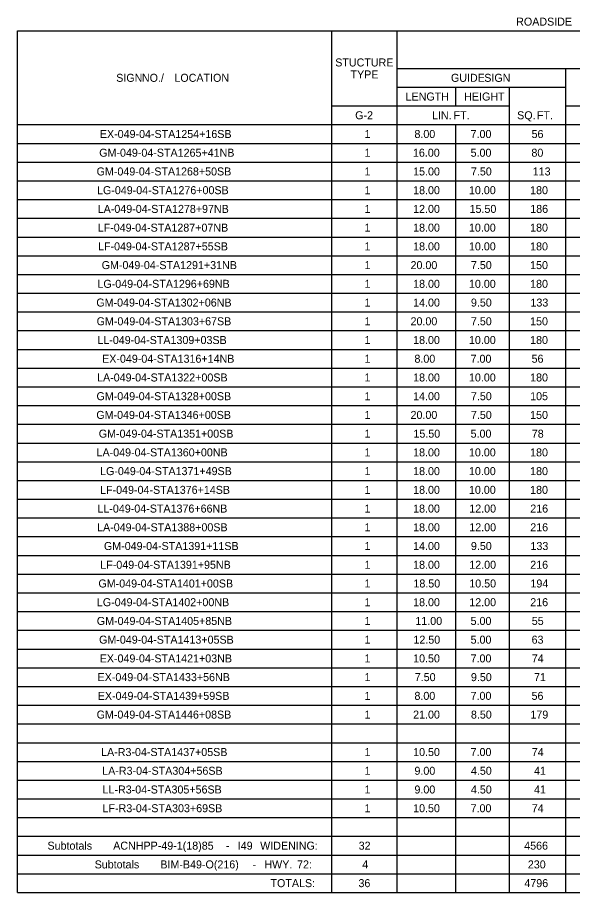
# Model space of a CAD drawing. Extents: x 1226631 to 1228126, y 151309 to 152305.
# Drawn here: x 1227303 to 1227650, y 151706 to 152253 of the extents above; entities that cross this region are included whole.
import ezdxf

# ---------------------------------------------------------------- set-up
doc = ezdxf.new("R2010")
doc.units = 0
doc.layers.add('R_Dimension', color=7, linetype='Continuous')

msp = doc.modelspace()

# ---------------------------------------------------------------- linework, layer by layer
at = {"layer": 'R_Dimension'}
for p, q in [((1227303.08, 152244.32), (1228086.49, 152244.32)), ((1227303.08, 151706.12), (1227303.08, 152244.32)), ((1227499.54, 151706.12), (1227499.54, 152244.32)), ((1227540.49, 151706.12), (1227540.49, 152244.32)), ((1227540.49, 152220.92), (1228086.49, 152220.92)), ((1227645.79, 151706.12), (1227645.79, 152220.92)), ((1227540.49, 152209.22), (1227645.79, 152209.22)), ((1227577.05, 152197.52), (1227577.05, 152209.22)), ((1227610.69, 151706.12), (1227610.69, 152209.22)), ((1227499.54, 152197.52), (1227610.69, 152197.52)), ((1227645.79, 152197.52), (1228026.04, 152197.52)), ((1227303.08, 152185.82), (1228086.49, 152185.82)), ((1227577.05, 151706.12), (1227577.05, 152185.82)), ((1227303.08, 152174.12), (1228086.49, 152174.12)), ((1227303.08, 152162.42), (1228086.49, 152162.42)), ((1227303.08, 152150.72), (1228086.49, 152150.72)), ((1227303.08, 152139.02), (1228086.49, 152139.02)), ((1227303.08, 152127.32), (1228086.49, 152127.32)), ((1227303.08, 152115.62), (1228086.49, 152115.62)), ((1227303.08, 152103.92), (1228086.49, 152103.92)), ((1227303.08, 152092.22), (1228086.49, 152092.22)), ((1227303.08, 152080.52), (1228086.49, 152080.52)), ((1227303.08, 152068.82), (1228086.49, 152068.82)), ((1227303.08, 152057.12), (1228086.49, 152057.12)), ((1227303.08, 152045.42), (1228086.49, 152045.42)), ((1227303.08, 152033.72), (1228086.49, 152033.72)), ((1227303.08, 152022.02), (1228086.49, 152022.02)), ((1227303.08, 152010.32), (1228086.49, 152010.32)), ((1227303.08, 151998.62), (1228086.49, 151998.62)), ((1227303.08, 151986.92), (1228086.49, 151986.92)), ((1227303.08, 151975.22), (1228086.49, 151975.22)), ((1227303.08, 151963.52), (1228086.49, 151963.52)), ((1227303.08, 151951.82), (1228086.49, 151951.82)), ((1227303.08, 151940.12), (1228086.49, 151940.12)), ((1227303.08, 151928.42), (1228086.49, 151928.42)), ((1227303.08, 151916.72), (1228086.49, 151916.72)), ((1227303.08, 151905.02), (1228086.49, 151905.02)), ((1227303.08, 151893.32), (1228086.49, 151893.32)), ((1227303.08, 151881.62), (1228086.49, 151881.62)), ((1227303.08, 151869.92), (1228086.49, 151869.92)), ((1227303.08, 151858.22), (1228086.49, 151858.22)), ((1227303.08, 151846.52), (1228086.49, 151846.52)), ((1227303.08, 151834.82), (1228086.49, 151834.82)), ((1227303.08, 151823.12), (1228086.49, 151823.12)), ((1227303.08, 151811.42), (1228086.49, 151811.42)), ((1227303.08, 151799.72), (1228086.49, 151799.72)), ((1227303.08, 151788.02), (1228086.49, 151788.02)), ((1227303.08, 151776.32), (1228086.49, 151776.32)), ((1227303.08, 151764.62), (1228086.49, 151764.62)), ((1227303.08, 151752.92), (1228086.49, 151752.92)), ((1227303.08, 151741.22), (1228086.49, 151741.22)), ((1227303.08, 151729.52), (1228086.49, 151729.52)), ((1227303.08, 151717.82), (1228086.49, 151717.82)), ((1227303.08, 151706.12), (1228086.49, 151706.12))]:
    msp.add_line(p, q, dxfattribs=at)

# ---------------------------------------------------------------- texts
for s, p in [('ROADSIDE', (1227614.82, 152247.67)), ('STUCTURE', (1227501.71, 152222.17)), ('TYPE', (1227511.28, 152214.67)), ('SIGN', (1227364.79, 152212.57)), (' NO./', (1227379.01, 152212.57)), (' LOCATION', (1227399.32, 152212.57)), ('GUIDE', (1227574.05, 152212.57)), (' SIGN', (1227593.02, 152212.57)), ('LENGTH', (1227545.7, 152200.87)), ('HEIGHT', (1227582.32, 152200.87)), ('G-2', (1227514.19, 152189.17)), ('LIN.', (1227562.19, 152189.17)), (' FT.', (1227573.84, 152189.17)), ('SQ.', (1227615.43, 152189.17)), (' FT.', (1227625.9, 152189.17)), ('EX-049-04-STA1254+16SB', (1227354.56, 152177.47)), ('1', (1227520.02, 152177.47)), ('8.00', (1227551.23, 152177.47)), ('7.00', (1227586.33, 152177.47)), ('56', (1227624.44, 152177.47)), ('GM-049-04-STA1265+41NB', (1227354.16, 152165.77)), ('1', (1227520.02, 152165.77)), ('16.00', (1227550.29, 152165.77)), ('5.00', (1227586.33, 152165.77)), ('80', (1227624.36, 152165.77)), ('GM-049-04-STA1268+50SB', (1227352.55, 152154.07)), ('1', (1227520.02, 152154.07)), ('15.00', (1227550.41, 152154.07)), ('7.50', (1227586.53, 152154.07)), ('113', (1227625.17, 152154.07)), ('LG-049-04-STA1276+00SB', (1227352.79, 152142.37)), ('1', (1227520.02, 152142.37)), ('18.00', (1227550.41, 152142.37)), ('10.00', (1227585.31, 152142.37)), ('180', (1227623.54, 152142.37)), ('LA-049-04-STA1278+97NB', (1227353.22, 152130.67)), ('1', (1227520.02, 152130.67)), ('12.00', (1227550.41, 152130.67)), ('15.50', (1227585.7, 152130.67)), ('186', (1227623.62, 152130.67)), ('LF-049-04-STA1287+07NB', (1227353.22, 152118.97)), ('1', (1227520.02, 152118.97)), ('18.00', (1227550.41, 152118.97)), ('10.00', (1227585.31, 152118.97)), ('180', (1227623.54, 152118.97)), ('LF-049-04-STA1287+55SB', (1227353.42, 152107.27)), ('1', (1227520.02, 152107.27)), ('18.00', (1227550.41, 152107.27)), ('10.00', (1227585.31, 152107.27)), ('180', (1227623.54, 152107.27)), ('GM-049-04-STA1291+31NB', (1227355.7, 152095.57)), ('1', (1227520.02, 152095.57)), ('20.00', (1227548.79, 152095.57)), ('7.50', (1227586.53, 152095.57)), ('150', (1227623.54, 152095.57)), ('LG-049-04-STA1296+69NB', (1227353.06, 152083.87)), ('1', (1227520.02, 152083.87)), ('18.00', (1227550.41, 152083.87)), ('10.00', (1227585.31, 152083.87)), ('180', (1227623.54, 152083.87)), ('GM-049-04-STA1302+06NB', (1227352.35, 152072.17)), ('1', (1227520.02, 152072.17)), ('14.00', (1227550.41, 152072.17)), ('9.50', (1227586.53, 152072.17)), ('133', (1227623.75, 152072.17)), ('GM-049-04-STA1303+67SB', (1227352.55, 152060.47)), ('20.00', (1227548.79, 152060.47)), ('7.50', (1227586.53, 152060.47)), ('150', (1227623.54, 152060.47)), ('1', (1227520.02, 152060.47)), ('LL-049-04-STA1309+03SB', (1227353.02, 152048.77)), ('1', (1227520.02, 152048.77)), ('18.00', (1227550.41, 152048.77)), ('10.00', (1227585.31, 152048.77)), ('180', (1227623.54, 152048.77)), ('EX-049-04-STA1316+14NB', (1227355.98, 152037.07)), ('1', (1227520.02, 152037.07)), ('8.00', (1227551.23, 152037.07)), ('7.00', (1227586.33, 152037.07)), ('56', (1227624.44, 152037.07)), ('LA-049-04-STA1322+00SB', (1227352.83, 152025.37)), ('1', (1227520.02, 152025.37)), ('18.00', (1227550.41, 152025.37)), ('10.00', (1227585.31, 152025.37)), ('180', (1227623.54, 152025.37)), ('GM-049-04-STA1328+00SB', (1227352.47, 152013.67)), ('1', (1227520.02, 152013.67)), ('14.00', (1227550.41, 152013.67)), ('7.50', (1227586.53, 152013.67)), ('105', (1227623.56, 152013.67)), ('GM-049-04-STA1346+00SB', (1227352.35, 152001.97)), ('1', (1227520.02, 152001.97)), ('20.00', (1227548.79, 152001.97)), ('7.50', (1227586.53, 152001.97)), ('150', (1227623.54, 152001.97)), ('GM-049-04-STA1351+00SB', (1227353.89, 151990.27)), ('1', (1227520.02, 151990.27)), ('15.50', (1227550.6, 151990.27)), ('5.00', (1227586.33, 151990.27)), ('78', (1227624.58, 151990.27)), ('LA-049-04-STA1360+00NB', (1227352.51, 151978.57)), ('1', (1227520.02, 151978.57)), ('18.00', (1227550.41, 151978.57)), ('10.00', (1227585.31, 151978.57)), ('180', (1227623.54, 151978.57)), ('LG-049-04-STA1371+49SB', (1227354.72, 151966.87)), ('1', (1227520.02, 151966.87)), ('18.00', (1227550.41, 151966.87)), ('10.00', (1227585.31, 151966.87)), ('180', (1227623.54, 151966.87)), ('LF-049-04-STA1376+14SB', (1227354.72, 151955.17)), ('1', (1227520.02, 151955.17)), ('18.00', (1227550.41, 151955.17)), ('10.00', (1227585.31, 151955.17)), ('180', (1227623.54, 151955.17)), ('LL-049-04-STA1376+66NB', (1227353.06, 151943.47)), ('1', (1227520.02, 151943.47)), ('18.00', (1227550.41, 151943.47)), ('12.00', (1227585.51, 151943.47)), ('216', (1227623.62, 151943.47)), ('LA-049-04-STA1388+00SB', (1227352.83, 151931.77)), ('1', (1227520.02, 151931.77)), ('18.00', (1227550.41, 151931.77)), ('12.00', (1227585.51, 151931.77)), ('216', (1227623.62, 151931.77)), ('GM-049-04-STA1391+11SB', (1227357.12, 151920.07)), ('1', (1227520.02, 151920.07)), ('14.00', (1227550.41, 151920.07)), ('9.50', (1227586.53, 151920.07)), ('133', (1227623.75, 151920.07)), ('LF-049-04-STA1391+95NB', (1227354.83, 151908.37)), ('1', (1227520.02, 151908.37)), ('18.00', (1227550.41, 151908.37)), ('12.00', (1227585.51, 151908.37)), ('216', (1227623.62, 151908.37)), ('GM-049-04-STA1401+00SB', (1227353.69, 151896.67)), ('1', (1227520.02, 151896.67)), ('18.50', (1227550.6, 151896.67)), ('10.50', (1227585.51, 151896.67)), ('194', (1227623.75, 151896.67)), ('LG-049-04-STA1402+00NB', (1227352.71, 151884.97)), ('1', (1227520.02, 151884.97)), ('18.00', (1227550.41, 151884.97)), ('12.00', (1227585.51, 151884.97)), ('216', (1227623.62, 151884.97)), ('GM-049-04-STA1405+85NB', (1227352.67, 151873.27)), ('1', (1227520.02, 151873.27)), ('11.00', (1227551.82, 151873.27)), ('5.00', (1227586.33, 151873.27)), ('55', (1227624.58, 151873.27)), ('GM-049-04-STA1413+05SB', (1227354.09, 151861.57)), ('1', (1227520.02, 151861.57)), ('12.50', (1227550.6, 151861.57)), ('5.00', (1227586.33, 151861.57)), ('63', (1227624.46, 151861.57)), ('EX-049-04-STA1421+03NB', (1227354.48, 151849.87)), ('1', (1227520.02, 151849.87)), ('10.50', (1227550.41, 151849.87)), ('7.00', (1227586.33, 151849.87)), ('74', (1227624.58, 151849.87)), ('EX-049-04-STA1433+56NB', (1227353.14, 151838.17)), ('1', (1227520.02, 151838.17)), ('7.50', (1227551.43, 151838.17)), ('9.50', (1227586.53, 151838.17)), ('71', (1227626, 151838.17)), ('EX-049-04-STA1439+59SB', (1227353.26, 151826.47)), ('1', (1227520.02, 151826.47)), ('8.00', (1227551.23, 151826.47)), ('7.00', (1227586.33, 151826.47)), ('56', (1227624.44, 151826.47)), ('GM-049-04-STA1446+08SB', (1227352.55, 151814.77)), ('1', (1227520.02, 151814.77)), ('21.00', (1227550.41, 151814.77)), ('8.50', (1227586.53, 151814.77)), ('179', (1227623.73, 151814.77)), ('LA-R3-04-STA1437+05SB', (1227355.35, 151791.37)), ('1', (1227520.02, 151791.37)), ('10.50', (1227550.41, 151791.37)), ('7.00', (1227586.33, 151791.37)), ('74', (1227624.58, 151791.37)), ('LA-R3-04-STA304+56SB', (1227356.05, 151779.67)), ('1', (1227520.02, 151779.67)), ('9.00', (1227551.23, 151779.67)), ('4.50', (1227586.53, 151779.67)), ('41', (1227626, 151779.67)), ('LL-R3-04-STA305+56SB', (1227356.25, 151767.97)), ('1', (1227520.02, 151767.97)), ('9.00', (1227551.23, 151767.97)), ('4.50', (1227586.53, 151767.97)), ('41', (1227626, 151767.97)), ('LF-R3-04-STA303+69SB', (1227356.25, 151756.27)), ('1', (1227520.02, 151756.27)), ('10.50', (1227550.41, 151756.27)), ('7.00', (1227586.33, 151756.27)), ('74', (1227624.58, 151756.27)), ('Subtotals', (1227321.83, 151732.87)), (' ACNHPP-49-1(18)85', (1227361.04, 151732.87)), (' I49', (1227438.92, 151732.87)), (' WIDENING:', (1227452.93, 151732.87)), ('32', (1227516.35, 151732.87)), ('4566', (1227619.84, 151732.87)), (' -', (1227431.47, 151732.87)), ('Subtotals', (1227351.32, 151721.17)), (' BIM-B49-O(216)', (1227390.53, 151721.17)), (' -', (1227448.13, 151721.17)), (' HWY.', (1227455.57, 151721.17)), (' 72:', (1227476, 151721.17)), ('4', (1227518.6, 151721.17)), ('230', (1227622.12, 151721.17)), ('TOTALS:', (1227461.24, 151709.47)), ('36', (1227516.22, 151709.47)), ('4796', (1227619.95, 151709.47))]:
    msp.add_text(s, height=5, dxfattribs=at).set_placement(p)

doc.saveas('drawing.dxf')
